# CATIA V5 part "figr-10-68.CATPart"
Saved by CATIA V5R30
Part number: Part1
Bounding box of the stored display mesh (mm): x -80.563 to 63.541, y -72 to 69, z -55 to 6.847
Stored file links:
  D:\PROJECTS\CATIA V56R 2020\Resources\Parts File\c10_catia_v5_6r2020_prt\figr-10-68.CATPart
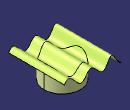
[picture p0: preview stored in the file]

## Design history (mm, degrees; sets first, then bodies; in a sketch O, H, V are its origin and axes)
Set1
  Sketch1 on xy-plane, origin (0, 0, 0), H (-1, 0, 0), V (0, -1, 0)
    circle A1 centre (0, 0) radius 45.985
  Extrude1: Element1 Sketch1, Lim1 56, Lim2 55, Direction xy-plane
  Sketch2 on zx-plane, origin (0, 0, 0), H (1, 0, 0), V (0, 0, -1)
    spline S1 through (-80.5635, 24.8913) (-73.6025, 19.8803) (-54.8525, -3.3629) (-35.1982, 19.8803) (-2.6271, -1.6506) (16.6996, 17.2854) (52.4104, -6.7877) (63.5409, 1.5862)
  Extrude2: Element1 Sketch2, Lim1 72, Lim2 69, Direction Sketch1.V
  Split1: ToCut Extrude1, Cutting Extrude2
Body1 (main body)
